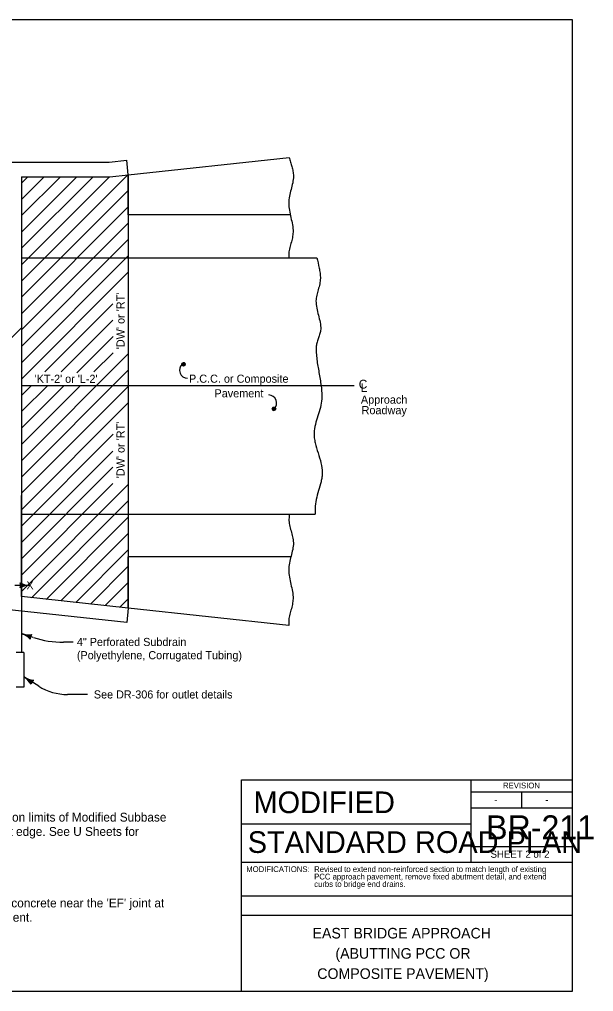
# Model space of a CAD drawing. Extents: x 9234 to 81668, y 5635 to 15999.
# Drawn here: x 26518 to 27712, y 7924 to 9944 of the extents above; entities that cross this region are included whole.
import ezdxf

# ---------------------------------------------------------------- set-up
doc = ezdxf.new("R2010")
doc.units = 0
for name, color, linetype in [('Alignment', 7, 'Continuous'), ('Level 61', 7, 'Continuous'), ('PS_BOLT', 7, 'Continuous'), ('PS_DIM', 7, 'Continuous'), ('Revetment', 7, 'Continuous'), ('SurEdgeShoulderUnpaved', 7, 'Continuous')]:
    doc.layers.add(name, color=color, linetype=linetype)

msp = doc.modelspace()

# ---------------------------------------------------------------- linework, layer by layer
at = {"layer": 'Level 61'}
msp.add_lwpolyline([(24532.5, 9944), (27667.5, 9944), (27667.5, 7924), (24532.5, 7924)], close=True, dxfattribs=at)
at = {"layer": 'PS_BOLT'}
for p, q in [((26539.5, 8768.1), (26508.2, 8768.1)), ((26629.4, 8649.8), (26609.8, 8649.8)), ((26557.9, 8558.6), (26527.3, 8577.8)), ((26659.5, 8541.4), (26617.9, 8541.4))]:
    msp.add_line(p, q, dxfattribs=at)
for centre, radius, start, end in [((26867.2, 9215.1), 16.5, 131.3092, 270), ((27036.2, 9147.2), 16.5, 311.309, 90), ((26609.8, 8855.4), 205.6, 252.1406, 270), ((26617.9, 8654.4), 113.1, 237.9168, 270)]:
    msp.add_arc(centre, radius, start, end, dxfattribs=at)
at = {"layer": 'PS_DIM'}
for p, q in [((25553.2, 9647.3), (26704.1, 9647.3)), ((26704.1, 9647.3), (26741, 9651.3)), ((26744.2, 9621.4), (26741, 9651.3)), ((26522.2, 9400.5), (26743, 9621.3)), ((26522.2, 9434.4), (26705, 9617.3)), ((26522.2, 9468.4), (26671.1, 9617.3)), ((26522.2, 9502.3), (26637.2, 9617.3)), ((26522.2, 9536.3), (26603.2, 9617.3)), ((26522.2, 9570.2), (26569.3, 9617.3)), ((26522.2, 9604.1), (26535.3, 9617.3)), ((26522.2, 9366.6), (26744.2, 9588.6)), ((26522.2, 9332.6), (26744.2, 9554.6)), ((26522.2, 9298.7), (26744.2, 9520.7)), ((26522.2, 9264.7), (26744.2, 9486.7)), ((26522.2, 9230.8), (26744.2, 9452.8)), ((26522.2, 9448.9), (26744.2, 9449)), ((26522.2, 9196.8), (26744.2, 9418.8)), ((26570.8, 9211.6), (26712.3, 9353.1)), ((26604.9, 9211.7), (26712.4, 9319.2)), ((26078.2, 8859.5), (26522.2, 9303.5)), ((26637, 9209.9), (26712.6, 9285.4)), ((26522.2, 9027.1), (26744.2, 9249.1)), ((26672.8, 9211.8), (26712.5, 9251.4)), ((26522.2, 8993.2), (26744.2, 9215.2)), ((26522.2, 9061.1), (26644.6, 9183.5)), ((26522.2, 9095), (26610.6, 9183.5)), ((26522.2, 9129), (26576.6, 9183.4)), ((26522.2, 9162.9), (26542.6, 9183.4)), ((26522.2, 8959.3), (26744.2, 9181.3)), ((26522.2, 8925.3), (26744.2, 9147.3)), ((26522.2, 8891.4), (26712.7, 9082)), ((26522.2, 8857.4), (26711.8, 9047.1)), ((26522.2, 8823.5), (26712.3, 9013.6)), ((26522.2, 8789.6), (26712.4, 8979.8)), ((26522.2, 8755.6), (26744.2, 8977.6)), ((26522.2, 8744.6), (26522.2, 8955)), ((26542.8, 8742.3), (26744.2, 8943.7)), ((26522.2, 8916.1), (26744.2, 8916.2)), ((26573.5, 8739), (26744.2, 8909.7)), ((26604.1, 8735.8), (26744.2, 8875.8)), ((26634.8, 8732.5), (26744.2, 8841.8)), ((26665.4, 8729.2), (26744.2, 8807.9)), ((26696.1, 8725.9), (26744.2, 8774)), ((26522.2, 8744.6), (26522.2, 8628.8)), ((26726.7, 8722.6), (26744.2, 8740)), ((26741, 8690.9), (26490, 8717.8)), ((26744.2, 8720.7), (26741, 8690.9)), ((26546.7, 8659.7), (26522.2, 8667.7)), ((26522.2, 8667.7), (26541, 8661.6)), ((26527.3, 8628.8), (26510.8, 8628.8)), ((26527.3, 8628.8), (26527.3, 8556.4)), ((26527.3, 8577.8), (26544, 8567.3)), ((26527.3, 8556.4), (26510.8, 8556.4))]:
    msp.add_line(p, q, dxfattribs=at)
for points in [[(26858.8, 9224.2), (26860, 9224.8), (26861.9, 9225.4), (26862.3, 9227.3), (26862, 9229), (26860.8, 9230.5), (26859, 9230.4), (26857.1, 9230.1), (26856.2, 9228.6), (26856, 9227), (26857.1, 9224.9), (26858.5, 9224.7), (26860.4, 9225.2), (26862, 9226.4), (26861.9, 9228.2), (26860.7, 9229.7), (26859, 9229.8), (26857.1, 9229.5), (26856.8, 9228.4), (26856.5, 9227.1), (26857.3, 9225.5), (26858.7, 9225.6), (26860.3, 9225.8), (26861.5, 9226.7), (26860.9, 9228.3), (26859.7, 9229.2), (26858.1, 9229.3), (26857.7, 9228.4), (26857.2, 9227.4), (26858, 9226.2), (26859.1, 9225.9), (26860.2, 9226.5), (26860.3, 9227.6), (26859.7, 9228.5), (26858.6, 9228.8), (26858.1, 9228.3), (26857.8, 9227.7), (26858.4, 9226.7), (26859.1, 9226.5), (26859.9, 9227), (26859.7, 9227.6), (26859.2, 9228), (26858.4, 9228), (26858.5, 9227.5), (26859.1, 9227.2)], [(27046.8, 9131.5), (27048, 9132), (27049.9, 9132.6), (27050.3, 9134.6), (27050, 9136.3), (27048.8, 9137.8), (27047, 9137.7), (27045.1, 9137.4), (27044.2, 9135.9), (27044, 9134.3), (27045.1, 9132.2), (27046.5, 9132), (27048.4, 9132.5), (27050, 9133.7), (27049.9, 9135.5), (27048.7, 9137), (27047, 9137.1), (27045.1, 9136.7), (27044.8, 9135.7), (27044.4, 9134.4), (27045.3, 9132.8), (27046.7, 9132.9), (27048.3, 9133.1), (27049.4, 9134), (27048.9, 9135.6), (27047.7, 9136.5), (27046.1, 9136.6), (27045.7, 9135.7), (27045.2, 9134.7), (27045.9, 9133.5), (27047.1, 9133.2), (27048.2, 9133.8), (27048.2, 9134.9), (27047.7, 9135.8), (27046.6, 9136), (27046.1, 9135.6), (27045.8, 9135), (27046.4, 9134), (27047.1, 9133.8), (27047.8, 9134.3), (27047.7, 9134.9), (27047.2, 9135.3), (27046.4, 9135.3), (27046.4, 9134.8), (27047.1, 9134.5)], [(26541.7, 8665.2), (26539.9, 8661.9), (26539.5, 8658.2), (26535.9, 8661.5), (26529.7, 8665.2), (26537.4, 8664.6), (26541, 8665), (26539.2, 8662.1), (26538.8, 8659.8), (26536.4, 8662), (26533, 8664.1), (26537.4, 8664), (26539.6, 8664), (26538.3, 8661.2), (26535.9, 8663.2), (26538.3, 8663.2), (26538, 8662.1), (26537.1, 8662.8)], [(26545.6, 8570.6), (26543.1, 8567.9), (26541.7, 8564.4), (26539.1, 8568.5), (26534, 8573.6), (26541.3, 8571.1), (26544.9, 8570.6), (26542.5, 8568.3), (26541.5, 8566.1), (26539.8, 8568.8), (26537, 8571.7), (26541.1, 8570.5), (26543.4, 8570), (26541.3, 8567.6), (26539.5, 8570.1), (26541.8, 8569.5), (26541.3, 8568.6), (26540.6, 8569.4)]]:
    msp.add_lwpolyline(points, dxfattribs=at)
for centre in [(26859.1, 9227.5), (27047.1, 9134.8)]:
    msp.add_circle(centre, 3.62, dxfattribs=at)
for centre, radius, start, end in [((26504.1, 8768.1), 16.3, 342.2666, 17.7333), ((26539.5, 8810.4), 42.3, 241.9275, 270), ((26539.5, 8725.8), 42.3, 90, 118.0725), ((26508.8, 8626.1), 43.7, 44.0691, 72.1415), ((26535.6, 8709.2), 43.7, 252.1415, 280.214), ((26557, 8656.4), 16.9, 144.4082, 179.8749), ((26504.1, 8540.8), 43.7, 29.8434, 57.9159), ((26550.5, 8614.8), 43.7, 237.9159, 265.9884), ((26558.3, 8558.3), 16.9, 130.1825, 165.6492)]:
    msp.add_arc(centre, radius, start, end, dxfattribs=at)
at = {"layer": 'Revetment'}
for p, q in [((26744.2, 9621.4), (27079.1, 9657.4)), ((26522.2, 9617.3), (26522.2, 8744.6)), ((26522.2, 9617.3), (26705.7, 9617.3)), ((26705.7, 9617.3), (26744.2, 9621.4)), ((26744.2, 9537.8), (26744.2, 9621.4)), ((26744.2, 9621.4), (26744.2, 9182.6)), ((26744.2, 9537.8), (26744.2, 9449)), ((27081.2, 9537.8), (26744.2, 9537.8)), ((26744.2, 9449), (27136.4, 9449)), ((26522.2, 9183.5), (26744.2, 9183.5)), ((26744.2, 9183.5), (27145.1, 9183.5)), ((26744.2, 9182.6), (26744.2, 8720.7)), ((27145.1, 9183.5), (27213.9, 9183.5)), ((26744.2, 8916.2), (27133.2, 8916.2)), ((26744.2, 8720.7), (26744.2, 8827.4)), ((27082.5, 8827.4), (26744.2, 8827.4)), ((26744.2, 8720.7), (26522.2, 8744.6)), ((27078.1, 8684.9), (26744.2, 8720.7))]:
    msp.add_line(p, q, dxfattribs=at)
for points in [[(27079.1, 9657.4), (27081.4, 9647.7), (27084.2, 9638.1), (27086.6, 9628.4), (27087.6, 9618.7), (27086.1, 9604.6), (27082.7, 9590.6), (27079.4, 9576.5), (27077.8, 9562.4), (27079.2, 9547.4), (27082.4, 9532.3), (27085.6, 9517.3), (27086.9, 9502.3), (27085.5, 9490.5), (27082.5, 9478.7), (27079.4, 9466.9), (27077.8, 9455.2), (27077.9, 9449)], [(27136.4, 9449), (27141.2, 9427.5), (27143, 9416.8), (27143.7, 9406.1), (27142.3, 9394.3), (27139.3, 9382.5), (27136.2, 9370.8), (27134.6, 9359), (27136, 9344.3), (27139.6, 9329.6), (27143.1, 9314.8), (27144.4, 9300.1), (27142.8, 9291.3), (27139.9, 9282.5), (27136.9, 9273.7), (27135.2, 9264.8), (27135.2, 9251.3), (27136.4, 9237.6), (27140.8, 9210.2), (27145.2, 9182.7), (27146.7, 9162.3), (27146.6, 9155.6), (27143.7, 9137.8), (27138.5, 9120.2), (27133.3, 9102.5), (27130.6, 9084.7), (27131.1, 9074.4), (27133, 9064), (27139, 9043.3), (27145, 9022.6), (27147.6, 9001.9), (27146.8, 8992.6), (27145.1, 8983.4), (27139.9, 8965), (27134.9, 8946.5), (27132.6, 8928), (27133.2, 8916.2)], [(27079.3, 8916.2), (27078.4, 8905.7), (27079.5, 8893.5), (27082.7, 8881.2), (27086, 8868.9), (27087.6, 8856.7), (27086.1, 8842.6), (27082.7, 8828.6), (27079.4, 8814.5), (27077.8, 8800.4), (27079.2, 8785.4), (27082.4, 8770.3), (27085.6, 8755.3), (27086.9, 8740.3), (27085.5, 8728.5), (27082.5, 8716.7), (27079.4, 8704.9), (27077.8, 8693.2), (27078.1, 8684.9)]]:
    msp.add_spline(points, degree=3, dxfattribs=at)
at = {"layer": 'SurEdgeShoulderUnpaved'}
for p, q in [((27456.6, 8364), (27456.6, 8272.7)), ((27456.6, 8339.1), (27667.5, 8339.1)), ((27562.1, 8339.1), (27562.1, 8305.9)), ((27456.6, 8305.9), (27667.5, 8305.9)), ((26979.5, 8272.7), (27456.6, 8272.7)), ((27456.6, 8272.7), (27456.6, 8192.7)), ((27667.5, 8224.9), (27456.6, 8224.9)), ((26979.5, 8192.7), (27667.5, 8192.7)), ((26979.5, 8122.7), (27667.5, 8122.7)), ((26979.5, 8082.7), (27667.5, 8082.7)), ((26979.5, 8082.7), (27667.5, 8082.7))]:
    msp.add_line(p, q, dxfattribs=at)
msp.add_lwpolyline([(26979.5, 8364), (27667.5, 8364), (27667.5, 7924), (26979.5, 7924)], close=True, dxfattribs=at)

# ---------------------------------------------------------------- texts
at = {"layer": 'Alignment'}
for s, height, p in [('MODIFIED', 45, (27004.6, 8294.8)), ('MODIFICATIONS:', 12, (26989.5, 8172.3))]:
    msp.add_text(s, height=height, dxfattribs=at).set_placement(p)
at = {"layer": 'PS_BOLT'}
for p in [(26736.5, 9258.7), (26736.5, 8990.6)]:
    msp.add_text("'DW' or 'RT'", height=16.884, rotation=90, dxfattribs=at).set_placement(p)
for s, height, p in [("'KT-2' or 'L-2'", 16.8, (26549.4, 9188.9)), ('P.C.C. or Composite', 16.884, (26870.4, 9189.1)), ('C', 18.5, (27223.5, 9176.8)), ('Pavement', 16.88, (26923.5, 9158.7)), ('L', 18.5, (27227.4, 9169.6)), ('Approach', 16.88, (27228, 9145.6)), ('Roadway', 16.88, (27229.4, 9123.7)), ('X', 16, (26532.7, 8760.1)), ('4" Perforated Subdrain ', 16.8, (26637.3, 8642.1)), ('(Polyethylene, Corrugated Tubing)', 16.8, (26637.3, 8614.6)), ('See DR-306 for outlet details', 16.8, (26672.6, 8533)), ('Polymer Grid and excavation limits of Modified Subbase', 18.375, (26214.4, 8277.2)), ('2 feet outside of pavement edge. See U Sheets for', 18.375, (26214.4, 8247.5)), ('Place an "X" in the plastic concrete near the \'EF\' joint at', 18.375, (26214.4, 8098.9)), ('the outside edge of pavement.', 18.375, (26214.4, 8069.2))]:
    msp.add_text(s, height=height, dxfattribs=at).set_placement(p)
at = {"layer": 'SurEdgeShoulderUnpaved'}
for s, height, p in [('REVISION', 12, (27523.6, 8346.2)), ('-', 15, (27505.1, 8314.7)), ('-', 15, (27611.6, 8315.1)), ('BR-211', 50, (27488.4, 8240.2)), ('STANDARD ROAD PLAN', 45.001, (26992.6, 8212.1)), ('SHEET 2 of 2', 15, (27497.6, 8202)), ('Revised to extend non-reinforced section to match length of existing ', 12, (27130.8, 8172.4)), ('PCC approach pavement, remove fixed abutment detail, and extend ', 12, (27130.8, 8156.9)), ('curbs to bridge end drains.', 12, (27130.8, 8141.4)), ('EAST BRIDGE APPROACH', 22, (27127.4, 8034.3)), ('(ABUTTING PCC OR', 22, (27175, 7992.3)), ('COMPOSITE PAVEMENT)', 22, (27137.3, 7950.3))]:
    msp.add_text(s, height=height, dxfattribs=at).set_placement(p)

doc.saveas('drawing.dxf')
